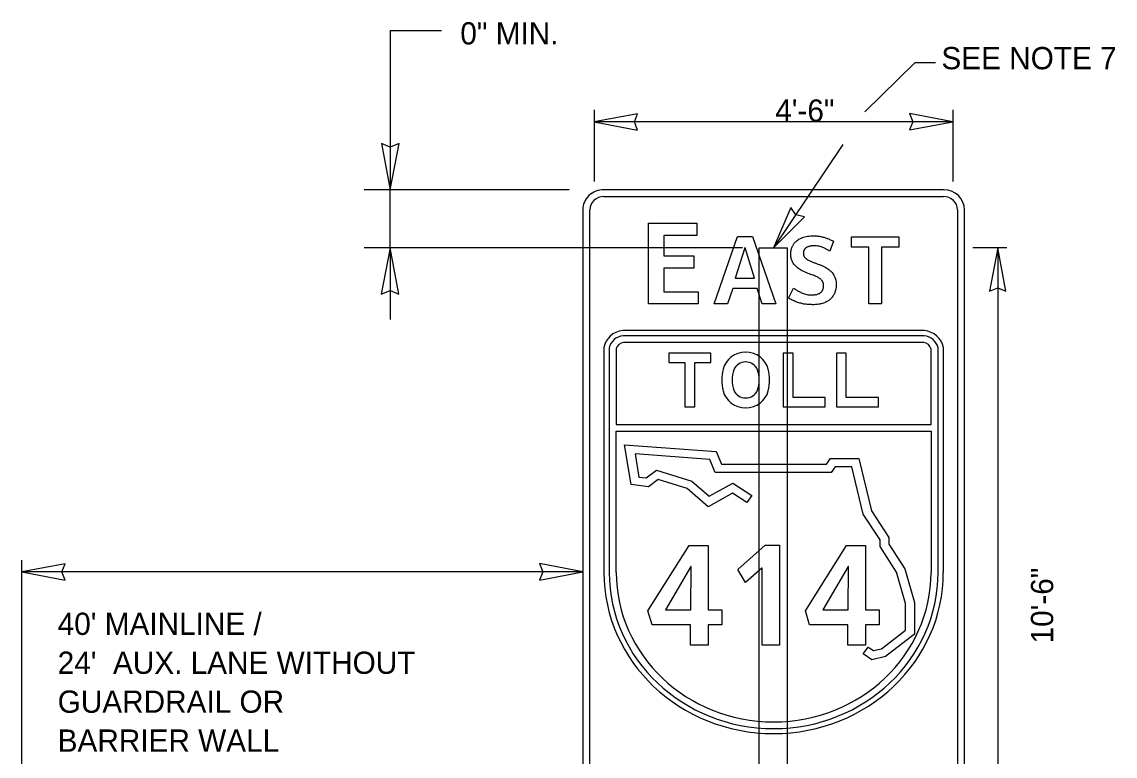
# Model space of a CAD drawing. Extents: x 34 to 667, y 20 to 415.
# Drawn here: x 100.2 to 237.8, y 316.8 to 409.3 of the extents above; entities that cross this region are included whole.
import ezdxf

# ---------------------------------------------------------------- set-up
doc = ezdxf.new("R2010")
doc.units = 0
for name, color, linetype in [('Default', 7, 'Continuous'), ('LeaderLine_dp', 7, 'Continuous'), ('SignPanel', 7, 'Continuous')]:
    doc.layers.add(name, color=color, linetype=linetype)

msp = doc.modelspace()

# ---------------------------------------------------------------- linework, layer by layer
at = {"layer": 'Default'}
for p, q in [((196.99, 385.91), (194.8, 380.82)), ((197.61, 385), (196.99, 385.91)), ((194.8, 380.82), (198.71, 384.75)), ((198.71, 384.75), (197.61, 385)), ((187.36, 373.8), (190.27, 382.25)), ((190.27, 382.25), (192.15, 382.25)), ((192.15, 382.25), (195.12, 373.8)), ((204.65, 380.93), (204.65, 382.23)), ((204.65, 382.23), (210.59, 382.23)), ((210.59, 382.23), (210.59, 380.93)), ((193.03, 280.79), (193.03, 380.82)), ((193.03, 380.82), (196.56, 380.82)), ((196.56, 280.79), (196.56, 380.82)), ((206.82, 380.93), (204.65, 380.93)), ((206.82, 373.8), (206.82, 380.93)), ((208.42, 380.93), (208.42, 373.8)), ((210.59, 380.93), (208.42, 380.93)), ((189.68, 375.72), (189.03, 373.8)), ((192.75, 375.72), (189.68, 375.72)), ((193.4, 373.8), (192.75, 375.72)), ((189.03, 373.8), (187.36, 373.8)), ((195.12, 373.8), (193.4, 373.8)), ((208.42, 373.8), (206.82, 373.8)), ((194.83, 369.77), (175.88, 369.77)), ((213.79, 369.77), (194.83, 369.77)), ((186.93, 367.57), (181.62, 367.57)), ((181.62, 367.57), (181.62, 366.39)), ((186.93, 367.57), (181.62, 367.57)), ((181.62, 367.57), (181.62, 366.39)), ((186.93, 366.39), (186.93, 367.57)), ((186.93, 366.39), (186.93, 367.57)), ((197.27, 367.57), (196.03, 367.57)), ((196.03, 367.57), (196.03, 360.81)), ((197.27, 367.57), (196.03, 367.57)), ((196.03, 367.57), (196.03, 360.81)), ((197.27, 361.99), (197.27, 367.57)), ((197.27, 361.99), (197.27, 367.57)), ((203.97, 367.57), (202.73, 367.57)), ((202.73, 367.57), (202.73, 360.81)), ((203.97, 367.57), (202.73, 367.57)), ((202.73, 367.57), (202.73, 360.81)), ((203.97, 361.99), (203.97, 367.57)), ((203.97, 361.99), (203.97, 367.57)), ((181.62, 366.39), (183.65, 366.39)), ((181.62, 366.39), (183.65, 366.39)), ((183.65, 366.39), (183.65, 360.81)), ((183.65, 366.39), (183.65, 360.81)), ((184.9, 360.81), (184.9, 366.39)), ((184.9, 366.39), (186.93, 366.39)), ((184.9, 360.81), (184.9, 366.39)), ((184.9, 366.39), (186.93, 366.39)), ((201.33, 361.99), (197.27, 361.99)), ((201.33, 361.99), (197.27, 361.99)), ((201.33, 360.81), (201.33, 361.99)), ((201.33, 360.81), (201.33, 361.99)), ((208.03, 361.99), (203.97, 361.99)), ((208.03, 361.99), (203.97, 361.99)), ((208.03, 360.81), (208.03, 361.99)), ((208.03, 360.81), (208.03, 361.99)), ((183.65, 360.81), (184.9, 360.81)), ((183.65, 360.81), (184.9, 360.81)), ((196.03, 360.81), (201.33, 360.81)), ((196.03, 360.81), (201.33, 360.81)), ((202.73, 360.81), (208.03, 360.81)), ((202.73, 360.81), (208.03, 360.81)), ((176.89, 351.02), (176.07, 356.03)), ((176.07, 356.03), (187.61, 355.19)), ((187.61, 355.19), (188.25, 353.61)), ((186.82, 354.19), (177.38, 354.88)), ((177.38, 354.88), (177.86, 351.97)), ((187.49, 352.56), (186.82, 354.19)), ((201.48, 353.61), (201.98, 354.31)), ((201.98, 354.31), (205.54, 354.31)), ((205.54, 354.31), (207.16, 347.73)), ((178.77, 351.87), (180.09, 352.85)), ((180.09, 352.85), (184.54, 351.47)), ((202.08, 352.56), (187.49, 352.56)), ((188.25, 353.61), (201.48, 353.61)), ((202.57, 353.26), (202.08, 352.56)), ((204.66, 353.26), (202.57, 353.26)), ((206.11, 347.32), (204.66, 353.26)), ((179.1, 350.76), (176.89, 351.02)), ((177.86, 351.97), (178.77, 351.87)), ((180.31, 351.67), (179.1, 350.76)), ((183.96, 350.54), (180.31, 351.67)), ((184.54, 351.47), (186.72, 349.55)), ((186.72, 349.55), (189.68, 351.2)), ((189.68, 351.2), (192.09, 349.65)), ((186.57, 348.24), (183.96, 350.54)), ((189.64, 349.95), (186.57, 348.24)), ((191.47, 348.78), (189.64, 349.95)), ((192.09, 349.65), (191.47, 348.78)), ((208.24, 344.08), (206.11, 347.32)), ((207.16, 347.73), (209.35, 344.38)), ((208.24, 343.24), (208.24, 344.08)), ((209.35, 344.38), (209.35, 343.53)), ((210.3, 340.01), (208.24, 343.24)), ((209.35, 343.53), (211.34, 340.43)), ((211.44, 336.04), (210.3, 340.01)), ((211.34, 340.43), (212.56, 336.18)), ((211.44, 332.71), (211.44, 336.04)), ((212.56, 336.18), (212.56, 332.21)), ((208.41, 330.35), (211.44, 332.71)), ((212.56, 332.21), (208.91, 329.37)), ((206.09, 329.7), (206.72, 330.57)), ((206.72, 330.57), (207.41, 330.12)), ((207.41, 330.12), (208.41, 330.35)), ((207.18, 328.98), (206.09, 329.7)), ((208.91, 329.37), (207.18, 328.98))]:
    msp.add_line(p, q, dxfattribs=at)
for points in [[(179.08, 373.8), (179.08, 383.92), (185.17, 383.92), (185.17, 382.37), (180.99, 382.37), (180.99, 379.82), (184.77, 379.82), (184.77, 378.26), (180.99, 378.26), (180.99, 375.31), (185.34, 375.31), (185.34, 373.8), (179.08, 373.8)], [(202.37, 381.66), (201.9, 380.39)], [(191.23, 380.82), (191.19, 380.82), (190, 376.99), (192.42, 376.99), (191.23, 380.82)], [(196.72, 374.5), (197.32, 375.76)], [(213.82, 370.41), (175.84, 370.41)], [(213.73, 368.93), (175.93, 368.93)], [(173.47, 368.29), (173.47, 339.97)], [(174.13, 368.24), (174.13, 339.97)], [(175.03, 368.15), (175.03, 358.57), (214.64, 358.57)], [(214.64, 358.57), (214.64, 368.15)], [(215.53, 339.97), (215.53, 368.24)], [(216.2, 339.97), (216.2, 368.29)], [(175.03, 339.97), (175.03, 357.73), (214.64, 357.73), (214.64, 339.97)], [(186.59, 333.37), (186.59, 330.81), (184.35, 330.81), (184.35, 333.37), (179.52, 333.37), (179.01, 335.13), (184.18, 343.34), (186.59, 343.34), (186.59, 335.26), (188.3, 335.26), (188.3, 333.37), (186.59, 333.37)], [(193.39, 330.81), (193.4, 340.49), (193.35, 340.49), (191.3, 338.68), (190.31, 340.32), (193.78, 343.39), (195.57, 343.39), (195.57, 330.81), (193.39, 330.81)], [(206.41, 333.37), (206.41, 330.81), (204.17, 330.81), (204.17, 333.37), (199.33, 333.37), (198.83, 335.13), (203.99, 343.34), (206.41, 343.34), (206.41, 335.26), (208.11, 335.26), (208.11, 333.37), (206.41, 333.37)], [(184.41, 340.73), (181.2, 335.26), (184.42, 335.26), (184.46, 340.73), (184.41, 340.73)], [(204.22, 340.73), (201.01, 335.26), (204.23, 335.26), (204.27, 340.73), (204.22, 340.73)]]:
    msp.add_lwpolyline(points, dxfattribs=at)
for points in [[(181.62, 366.39), (183.65, 366.39), (183.65, 360.81), (184.9, 360.81), (184.9, 366.39), (186.93, 366.39), (186.93, 367.57), (181.62, 367.57)], [(201.33, 360.81), (201.33, 361.99), (197.27, 361.99), (197.27, 367.57), (196.03, 367.57), (196.03, 360.81)], [(208.03, 360.81), (208.03, 361.99), (203.97, 361.99), (203.97, 367.57), (202.73, 367.57), (202.73, 360.81)]]:
    msp.add_lwpolyline(points, close=True, dxfattribs=at)
for centre, major_axis, start_param, end_param in [((176.1, 367.88), (2.67, 0), 1.668878, 2.979017), ((213.56, 367.88), (2.67, 0), 0.162576, 1.472714), ((176.1, 367.88), (2, 0), 1.684067, 2.953797), ((176.1, 367.88), (1.11, 0), 1.72283, 2.88934), ((213.56, 367.88), (1.11, 0), 0.252252, 1.418763), ((213.56, 367.88), (2, 0), 0.187795, 1.457526), ((191.27, 364.95), (2.87, 0), 1.556517, 2.923458), ((191.27, 364.95), (2.87, 0), 1.556517, 2.923458), ((191.27, 364.95), (2.87, 0), 1.556517, 2.923458), ((191.35, 364.95), (2.87, 0), 0.218134, 1.585075), ((191.35, 364.95), (2.87, 0), 0.218134, 1.585075), ((191.35, 364.95), (2.87, 0), 0.218134, 1.585075), ((191.32, 364.92), (1.62, 0), 1.578746, 2.762765), ((191.32, 364.92), (1.62, 0), 1.578746, 2.762765), ((191.32, 364.92), (1.62, 0), 1.578746, 2.762765), ((191.3, 364.92), (1.62, 0), 0.378827, 1.562847), ((191.3, 364.92), (1.62, 0), 0.378827, 1.562847), ((191.3, 364.92), (1.62, 0), 0.378827, 1.562847), ((195.36, 364.16), (7.04, 0), 2.93356, 3.136663), ((195.36, 364.16), (7.04, 0), 2.93356, 3.136663), ((195.36, 364.16), (7.04, 0), 2.93356, 3.136663), ((193.96, 364.2), (4.35, 0), 2.825907, 3.14372), ((193.96, 364.2), (4.35, 0), 2.825907, 3.14372), ((193.96, 364.2), (4.35, 0), 2.825907, 3.14372), ((188.66, 364.2), (4.35, 0), 6.281058, 6.598871), ((188.66, 364.2), (4.35, 0), 6.281058, 6.598871), ((188.66, 364.2), (4.35, 0), 6.281058, 6.598871), ((187.27, 364.16), (7.04, 0), 0.00493, 0.208032), ((187.27, 364.16), (7.04, 0), 0.00493, 0.208032), ((187.27, 364.16), (7.04, 0), 0.00493, 0.208032), ((195.36, 364.23), (7.04, 0), 3.146522, 3.349625), ((195.36, 364.23), (7.04, 0), 3.146522, 3.349625), ((195.36, 364.23), (7.04, 0), 3.146522, 3.349625), ((193.96, 364.18), (4.35, 0), 3.139465, 3.457279), ((193.96, 364.18), (4.35, 0), 3.139465, 3.457279), ((193.96, 364.18), (4.35, 0), 3.139465, 3.457279), ((188.66, 364.18), (4.35, 0), 5.967499, 6.285313), ((188.66, 364.18), (4.35, 0), 5.967499, 6.285313), ((188.66, 364.18), (4.35, 0), 5.967499, 6.285313), ((187.27, 364.23), (7.04, 0), 6.075153, 6.278256), ((187.27, 364.23), (7.04, 0), 6.075153, 6.278256), ((187.27, 364.23), (7.04, 0), 6.075153, 6.278256), ((191.27, 363.43), (2.87, 0), 3.359727, 4.726668), ((191.27, 363.43), (2.87, 0), 3.359727, 4.726668), ((191.27, 363.43), (2.87, 0), 3.359727, 4.726668), ((191.32, 363.47), (1.62, 0), 3.52042, 4.704439), ((191.32, 363.47), (1.62, 0), 3.52042, 4.704439), ((191.32, 363.47), (1.62, 0), 3.52042, 4.704439), ((191.3, 363.47), (1.62, 0), 4.720339, 5.904358), ((191.3, 363.47), (1.62, 0), 4.720559, 5.904358), ((191.3, 363.47), (1.62, 0), 4.720559, 5.904358), ((191.35, 363.43), (2.87, 0), 4.69811, 6.065051), ((191.35, 363.43), (2.87, 0), 4.698234, 6.065051), ((191.35, 363.43), (2.87, 0), 4.698234, 6.065051), ((194.83, 339.97), (21.36, 0), 3.141593, 6.283185), ((194.83, 339.97), (20.7, 0), 3.141593, 4.712389), ((194.83, 339.97), (19.81, 0), 3.141593, 4.712389), ((194.83, 339.97), (20.7, 0), 4.712406, 6.283185), ((194.83, 339.97), (19.81, 0), 4.712407, 6.283185)]:
    msp.add_ellipse(centre, major_axis=major_axis, ratio=0.949725, start_param=start_param, end_param=end_param, dxfattribs=at)
for points in [[(196.99, 380.06), (196.99, 380.11), (196.99, 380.25), (197.02, 380.48), (197.08, 380.74), (197.15, 380.95), (197.23, 381.09), (197.31, 381.23), (197.42, 381.4), (197.58, 381.58), (197.73, 381.71), (197.89, 381.83), (198.13, 381.98), (198.44, 382.12), (198.76, 382.21), (199.1, 382.29), (199.45, 382.34), (199.72, 382.34), (199.81, 382.34)], [(199.81, 382.34), (199.93, 382.34), (200.27, 382.33), (200.72, 382.27), (201.15, 382.16), (201.57, 382.03), (201.98, 381.86), (202.27, 381.71), (202.37, 381.66)], [(199.52, 377.49), (199.37, 377.55), (199.07, 377.66), (198.7, 377.81), (198.34, 377.97), (198.07, 378.13), (197.85, 378.29), (197.7, 378.42), (197.53, 378.58), (197.36, 378.79), (197.24, 378.99), (197.15, 379.17), (197.08, 379.37), (197.02, 379.63), (196.99, 379.86), (196.99, 380.01), (196.99, 380.06)], [(199.93, 381.08), (199.84, 381.08), (199.7, 381.08), (199.53, 381.06), (199.41, 381.04), (199.25, 381), (199.12, 380.95), (199.02, 380.9), (198.98, 380.88), (198.92, 380.84), (198.85, 380.78), (198.77, 380.71), (198.72, 380.64), (198.68, 380.57), (198.64, 380.51), (198.61, 380.42), (198.58, 380.31), (198.57, 380.2), (198.57, 380.14), (198.57, 380.12)], [(198.57, 380.12), (198.57, 380.1), (198.57, 380.04), (198.58, 379.94), (198.62, 379.83), (198.66, 379.74), (198.71, 379.68), (198.8, 379.57), (198.93, 379.45), (199.09, 379.34), (199.31, 379.22), (199.6, 379.09), (199.96, 378.96), (200.18, 378.88), (200.29, 378.83)], [(201.9, 380.39), (201.83, 380.44), (201.61, 380.59), (201.29, 380.76), (201.02, 380.88), (200.82, 380.96), (200.56, 381.03), (200.25, 381.07), (200.02, 381.08), (199.93, 381.08)], [(200.29, 378.83), (200.43, 378.78), (200.72, 378.67), (201.07, 378.52), (201.42, 378.35), (201.68, 378.18), (201.89, 378.02), (202.03, 377.89), (202.19, 377.72), (202.35, 377.5), (202.47, 377.3), (202.55, 377.12), (202.62, 376.91), (202.69, 376.6), (202.7, 376.37), (202.7, 376.22)], [(201.12, 376.07), (201.12, 376.09), (201.12, 376.16), (201.11, 376.27), (201.08, 376.4), (201.04, 376.51), (201, 376.58), (200.95, 376.65), (200.87, 376.76), (200.77, 376.87), (200.64, 376.97), (200.49, 377.07), (200.32, 377.17), (200.08, 377.28), (199.83, 377.38), (199.62, 377.45), (199.52, 377.49)], [(197.32, 375.76), (197.41, 375.71), (197.67, 375.53), (198.03, 375.32), (198.36, 375.17), (198.6, 375.07), (198.85, 374.99), (199.16, 374.92), (199.43, 374.9), (199.59, 374.89), (199.64, 374.89)], [(199.64, 374.89), (199.69, 374.89), (199.83, 374.9), (200.01, 374.92), (200.19, 374.95), (200.36, 374.99), (200.52, 375.06), (200.65, 375.13), (200.74, 375.19), (200.81, 375.26), (200.9, 375.35), (200.96, 375.43), (201, 375.5), (201.04, 375.58), (201.08, 375.69), (201.12, 375.86), (201.12, 375.99), (201.12, 376.07)], [(202.7, 376.22), (202.7, 376.11), (202.69, 375.85), (202.63, 375.51), (202.55, 375.23), (202.48, 375.06), (202.4, 374.91), (202.29, 374.73), (202.13, 374.53), (201.98, 374.38), (201.85, 374.27), (201.71, 374.17), (201.53, 374.06), (201.25, 373.92), (200.94, 373.82), (200.52, 373.73), (200.13, 373.68), (199.82, 373.67), (199.72, 373.67)], [(199.72, 373.67), (199.58, 373.68), (199.17, 373.68), (198.63, 373.75), (198.13, 373.87), (197.64, 374.03), (197.17, 374.24), (196.83, 374.43), (196.72, 374.5)]]:
    msp.add_open_spline(points, degree=3, dxfattribs=at)
at = {"layer": 'LeaderLine_dp'}
for p, q in [((146.56, 408.19), (146.56, 388.15)), ((146.56, 408.19), (153.02, 408.19)), ((172.26, 398.19), (172.26, 389.2)), ((217.38, 396.69), (211.93, 397.74)), ((211.93, 397.74), (212.34, 396.69)), ((217.38, 398.19), (217.38, 389.2)), ((177.71, 397.71), (172.26, 396.69)), ((172.26, 396.69), (177.71, 395.64)), ((217.38, 396.69), (172.26, 396.69)), ((177.3, 396.69), (177.71, 397.71)), ((177.71, 395.64), (177.3, 396.69)), ((212.34, 396.69), (211.93, 395.68)), ((211.93, 395.68), (217.38, 396.69)), ((146.56, 393.51), (145.48, 393.95)), ((145.48, 393.95), (146.56, 388.15)), ((146.56, 388.15), (147.69, 393.95)), ((147.69, 393.95), (146.56, 393.51)), ((169.11, 388.15), (143.27, 388.15)), ((146.56, 380.82), (146.56, 388.15)), ((190.93, 380.82), (143.27, 380.82)), ((146.56, 380.82), (145.44, 375.01)), ((147.65, 375.01), (146.56, 380.82)), ((146.56, 380.82), (146.56, 371.82)), ((224.17, 380.82), (219.89, 380.82)), ((223.05, 380.82), (222, 375.36)), ((223.05, 380.82), (223.05, 280.79)), ((224.07, 375.36), (223.05, 380.82)), ((222, 375.36), (223.05, 375.78)), ((223.05, 375.78), (224.07, 375.36)), ((145.44, 375.01), (146.56, 375.45)), ((146.56, 375.45), (147.65, 375.01)), ((100.2, 237.54), (100.2, 341.53)), ((105.65, 341.04), (100.2, 340.03)), ((170.8, 340.03), (100.2, 340.03)), ((100.2, 340.03), (105.65, 338.98)), ((105.24, 340.03), (105.65, 341.04)), ((105.65, 338.98), (105.24, 340.03)), ((170.8, 340.03), (165.35, 341.08)), ((165.35, 341.08), (165.76, 340.03)), ((165.76, 340.03), (165.35, 339.01)), ((165.35, 339.01), (170.8, 340.03))]:
    msp.add_line(p, q, dxfattribs=at)
for points in [[(215.21, 404.1), (212.59, 404.1), (206.29, 397.97)], [(203.54, 393.82), (194.8, 380.82)]]:
    msp.add_lwpolyline(points, dxfattribs=at)
at = {"layer": 'SignPanel'}
for p, q in [((216.2, 388.15), (173.47, 388.15)), ((173.47, 387.3), (216.2, 387.3)), ((170.8, 385.61), (170.8, 284.16)), ((171.69, 284.16), (171.69, 385.61)), ((217.98, 385.61), (217.98, 284.16)), ((218.87, 284.16), (218.87, 385.61))]:
    msp.add_line(p, q, dxfattribs=at)
for centre, major_axis, start_param, end_param in [((173.47, 385.61), (2.67, 0), 1.570796, 3.141593), ((216.2, 385.61), (2.67, 0), 0, 1.570796), ((173.47, 385.61), (1.78, 0), 1.570796, 3.141593), ((216.2, 385.61), (1.78, 0), 0, 1.570796)]:
    msp.add_ellipse(centre, major_axis=major_axis, ratio=0.949725, start_param=start_param, end_param=end_param, dxfattribs=at)

# ---------------------------------------------------------------- texts
at = {"layer": 'Default'}
for s, rotation, p in [('0" MIN.', 360, (155.39, 406.43)), ('SEE NOTE 7', 0, (215.95, 403.31)), ('4\'-6"', 0, (195.03, 396.71)), ('10\'-6"', 90, (230.02, 331.03)), ("40' MAINLINE /", 0, (104.71, 332.1)), ("24'  AUX. LANE WITHOUT", 0, (104.71, 327.2)), ('GUARDRAIL OR ', 0, (104.71, 322.3)), ('BARRIER WALL', 0, (104.71, 317.4))]:
    msp.add_text(s, height=2.8, rotation=rotation, dxfattribs=at).set_placement(p)

doc.saveas('drawing.dxf')
